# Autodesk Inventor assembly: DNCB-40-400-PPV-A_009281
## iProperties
Created: 2005-05
Part Number: DNCB-40-400-PPV-A_009281
Document SubType Name: Assembly
Designer: tfa
Manufacturer: Standard
Standards Organization: Custom
Author: tfa
